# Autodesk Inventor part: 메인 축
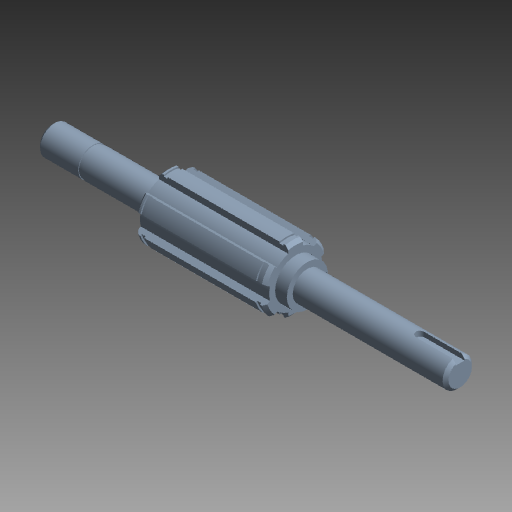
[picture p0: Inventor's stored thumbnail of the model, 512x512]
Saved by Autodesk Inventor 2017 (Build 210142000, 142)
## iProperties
Created: 2021-07
Part Number: 메인 축
Document SubType Name: 모델링
Designer: mdu
Mass: 168.566 g
Surface Area: 72.5104 cm^2
Volume: 21.4461 cm^3
Density: 7.86 g/cm^3
Material: 강철, 연강
Appearance: 연한 강청색
변환 표준: STEP AP214IS
파일 이름: C:\Users\SeoGD\Desktop\?쒗뿕\硫붿씤 異?.stp
전처리기: Build: 253, Release: 2010 SP1 - Date: Wed 07/29/2009
전송 단위: 밀리미터
불확실성: 0.01
Author: mdu
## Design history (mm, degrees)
sketch "스케치1"
  geometry: L1 (-69.5, 0)-(69.5, 0); L2 (69.5, 0)-(69.5, 5); L3 (69.5, 5)-(55.5, 5); L4 (55.5, 5)-(55.5, 4.8); L5 (55.5, 4.8)-(54.35, 4.8); L6 (54.35, 4.8)-(54.35, 5); L7 (54.35, 5)-(30.5, 5); L8 (30.5, 5)-(30.5, 9); L9 (30.5, 9)-(-13.5, 9); L10 (-13.5, 9)-(-13.5, 7); L11 (-13.5, 7)-(-17.5, 7); L12 (-17.5, 7)-(-17.5, 5); L13 (-17.5, 5)-(-69.5, 5); L14 (-69.5, 5)-(-69.5, 0); 2 further points
  constraints: 28 end point, 9 parallel, 4 collinear, 2 perpendicular, 1 coincident, 1 horizontal, 1 midpoint
  dimensions: "d2" = 1.15 distance between parallel lines of L6 L4; "d3" = 10 diameter of L3 L1; "d4" = 9.6 diameter of L5 L1; "d6" = 44 distance between parallel lines of L10 L8; "d7" = 4 distance between parallel lines of L12 L10; "d8" = 14 diameter of L11 L1; "d9" = 18 diameter of L9 L1; "d33" = 52 distance from line of L12.end L14; "d37" = 39 distance between parallel lines of L8 L2; "d38" = 14 distance between parallel lines of L2 L4
revolve "회전1" sketch "스케치1" stored, may be unused: angle "d10" = 90 deg
sketch "스케치2"
  geometry: L1 (2.5, 10.712)-(2.5, 8.646); L2 (-2.5, 10.712)-(-2.5, 8.646); A1 r 9 centre (0, 0) between (2.5, 8.646) and (-2.5, 8.646) reference; A2 r 11 centre (0, 0) between (2.5, 10.712) and (-2.5, 10.712); 1 further point
  constraints: 4 end point, 4 point on circle, 2 parallel, 1 centre point, 1 coincident, 1 vertical
  dimensions: "d11" = 22 diameter of A2; "d12" = 5 distance between parallel lines of L1 L2
extrude "돌출1" join sketch "스케치2" stored distance "d13" = 10; taper "d14" = 0 deg
chamfer "모따기1" distance "d15" = 1; stored, may be unused: second distance "d16" = 2, angle "d17" = 45 deg
node "작업 평면1"
node "작업 평면2"
sketch "스케치3"
  geometry: L1 (2.5, 10.712)-(2.5, 10.198); L2 (-2.5, 10.712)-(-2.5, 10.198); A1 r 11 centre (0, 0) between (2.5, 10.712) and (-2.5, 10.712) reference; A2 r 10.5 centre (0, 0) between (2.5, 10.198) and (-2.5, 10.198); 1 further point
  constraints: 4 end point, 2 point on circle, 1 centre point, 1 coincident, 1 parallel, 1 vertical
  dimensions: "d19" = 21 diameter of A2
extrude "돌출2" cut sketch "스케치3" distance "d20" = 1.35; taper "d21" = 0 deg
node "작업 평면3"
sketch "스케치4"
  geometry: L1 (-26, -5)-(-26, 5) reference; L2 (-26, 1.5)-(-12.5, 1.5); L3 (-12.5, -1.5)-(-26, -1.5); A1 r 1.5 centre (-12.5, 0) between (-12.5, -1.5) and (-12.5, 1.5); 2 further points
  constraints: 4 end point, 2 perpendicular, 2 point on circle, 2 point on line, 2 tangent, 1 centre point, 1 horizontal alignment, 1 midpoint
  dimensions: "d25" = 3 distance between parallel lines of L3 L2; "d26" = 15 dimension on A1 L1
extrude "돌출3" cut sketch "스케치4" distance "d27" = 1.8; taper "d28" = 0 deg
chamfer "모따기2" distance "d29" = 1; stored, may be unused: second distance "d30" = 2, angle "d31" = 45 deg
node "솔리드1"
node "솔리드 본체"
node "곡면 본체"
mirror "대칭1"
pattern_circular "원형 패턴1" dims "d23" = 360 deg
node "솔리드2"
other parameters: "d18" = -1.65
